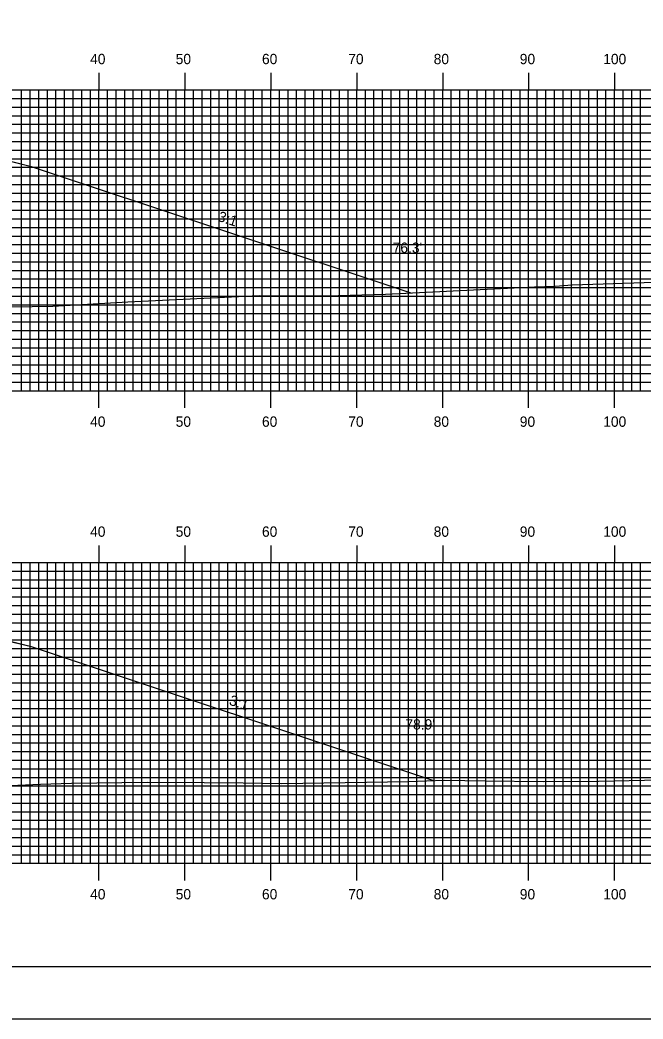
# Model space of a CAD drawing. Extents: x 1781860 to 1782203, y 442591 to 442811.
# Drawn here: x 1782056.7 to 1782129.2, y 442590.5 to 442706.8 of the extents above; entities that cross this region are included whole.
import ezdxf

# ---------------------------------------------------------------- set-up
doc = ezdxf.new("R2010")
doc.units = 0
for name, color, linetype in [('ANNOTATION', 7, 'Continuous'), ('BORDER', 7, 'Continuous'), ('D_Roadway_Centerline', 7, 'Continuous'), ('D_Roadway_SlopeLines', 7, 'Continuous'), ('D_Text_Standard', 7, 'Continuous'), ('H_V ANNOTATION', 7, 'Continuous'), ('MAJOR', 7, 'Continuous'), ('MINOR', 7, 'Continuous'), ('PLOT BOUNDARY', 7, 'Continuous'), ('S_Roadway_Centerline', 7, 'Continuous')]:
    doc.layers.add(name, color=color, linetype=linetype)

msp = doc.modelspace()

# ---------------------------------------------------------------- linework, layer by layer
at = {"layer": 'BORDER'}
msp.add_lwpolyline([(1781876.32, 442596.67), (1782196.32, 442596.67), (1782196.32, 442806.67), (1781876.32, 442806.67)], close=True, dxfattribs=at)
at = {"layer": 'D_Roadway_Centerline'}
for points in [[(1781943.58, 442673.02), (1781993.92, 442689.8), (1781995.75, 442690.26), (1782005.92, 442692.8), (1782013.92, 442693.12), (1782025.92, 442693.36), (1782037.92, 442693.12), (1782045.92, 442692.8), (1782056.09, 442690.26), (1782057.92, 442689.8), (1782102.21, 442675.04)], [(1781946.27, 442618.04), (1781993.92, 442633.93), (1781995.75, 442634.38), (1782005.92, 442636.93), (1782013.92, 442637.25), (1782025.92, 442637.49), (1782037.92, 442637.25), (1782045.92, 442636.93), (1782056.09, 442634.38), (1782057.92, 442633.93), (1782104.84, 442618.29)]]:
    msp.add_lwpolyline(points, dxfattribs=at)
at = {"layer": 'D_Roadway_SlopeLines'}
for points in [[(1782045.92, 442692.8), (1782057.92, 442689.8), (1782102.21, 442675.04)], [(1782045.92, 442636.93), (1782057.92, 442633.93), (1782104.84, 442618.29)]]:
    msp.add_lwpolyline(points, dxfattribs=at)
at = {"layer": 'MAJOR'}
for p, q in [((1782065.92, 442700.67), (1782065.92, 442698.67)), ((1782075.92, 442700.67), (1782075.92, 442698.67)), ((1782085.92, 442700.67), (1782085.92, 442698.67)), ((1782095.92, 442700.67), (1782095.92, 442698.67)), ((1782105.92, 442700.67), (1782105.92, 442698.67)), ((1782115.92, 442700.67), (1782115.92, 442698.67)), ((1782125.92, 442700.67), (1782125.92, 442698.67)), ((1781885.92, 442698.67), (1782165.92, 442698.67)), ((1781885.92, 442698.67), (1782165.92, 442698.67)), ((1782065.92, 442663.67), (1782065.92, 442698.67)), ((1782075.92, 442663.67), (1782075.92, 442698.67)), ((1782085.92, 442663.67), (1782085.92, 442698.67)), ((1782095.92, 442663.67), (1782095.92, 442698.67)), ((1782105.92, 442663.67), (1782105.92, 442698.67)), ((1782115.92, 442663.67), (1782115.92, 442698.67)), ((1782125.92, 442663.67), (1782125.92, 442698.67)), ((1781885.92, 442693.67), (1782165.92, 442693.67)), ((1781885.92, 442688.67), (1782165.92, 442688.67)), ((1781885.92, 442683.67), (1782165.92, 442683.67)), ((1781885.92, 442678.67), (1782165.92, 442678.67)), ((1781885.92, 442673.67), (1782165.92, 442673.67)), ((1781885.92, 442668.67), (1782165.92, 442668.67)), ((1781885.92, 442663.67), (1782165.92, 442663.67)), ((1781885.92, 442663.67), (1782165.92, 442663.67)), ((1782065.92, 442661.66), (1782065.92, 442663.67)), ((1782075.92, 442661.66), (1782075.92, 442663.67)), ((1782085.92, 442661.66), (1782085.92, 442663.67)), ((1782095.92, 442661.66), (1782095.92, 442663.67)), ((1782105.92, 442661.66), (1782105.92, 442663.67)), ((1782115.92, 442661.66), (1782115.92, 442663.67)), ((1782125.92, 442661.66), (1782125.92, 442663.67)), ((1782065.92, 442645.67), (1782065.92, 442643.67)), ((1782075.92, 442645.67), (1782075.92, 442643.67)), ((1782085.92, 442645.67), (1782085.92, 442643.67)), ((1782095.92, 442645.67), (1782095.92, 442643.67)), ((1782105.92, 442645.67), (1782105.92, 442643.67)), ((1782115.92, 442645.67), (1782115.92, 442643.67)), ((1782125.92, 442645.67), (1782125.92, 442643.67)), ((1781885.92, 442643.67), (1782165.92, 442643.67)), ((1781885.92, 442643.67), (1782165.92, 442643.67)), ((1782065.92, 442608.67), (1782065.92, 442643.67)), ((1782075.92, 442608.67), (1782075.92, 442643.67)), ((1782085.92, 442608.67), (1782085.92, 442643.67)), ((1782095.92, 442608.67), (1782095.92, 442643.67)), ((1782105.92, 442608.67), (1782105.92, 442643.67)), ((1782115.92, 442608.67), (1782115.92, 442643.67)), ((1782125.92, 442608.67), (1782125.92, 442643.67)), ((1781885.92, 442638.67), (1782165.92, 442638.67)), ((1781885.92, 442633.67), (1782165.92, 442633.67)), ((1781885.92, 442628.67), (1782165.92, 442628.67)), ((1781885.92, 442623.67), (1782165.92, 442623.67)), ((1781885.92, 442618.67), (1782165.92, 442618.67)), ((1781885.92, 442613.67), (1782165.92, 442613.67)), ((1781885.92, 442608.67), (1782165.92, 442608.67)), ((1781885.92, 442608.67), (1782165.92, 442608.67)), ((1782065.92, 442606.66), (1782065.92, 442608.67)), ((1782075.92, 442606.66), (1782075.92, 442608.67)), ((1782085.92, 442606.66), (1782085.92, 442608.67)), ((1782095.92, 442606.66), (1782095.92, 442608.67)), ((1782105.92, 442606.66), (1782105.92, 442608.67)), ((1782115.92, 442606.66), (1782115.92, 442608.67)), ((1782125.92, 442606.66), (1782125.92, 442608.67))]:
    msp.add_line(p, q, dxfattribs=at)
at = {"layer": 'MINOR'}
for p, q in [((1782056.92, 442663.67), (1782056.92, 442698.67)), ((1782057.92, 442663.67), (1782057.92, 442698.67)), ((1782058.92, 442663.67), (1782058.92, 442698.67)), ((1782059.92, 442663.67), (1782059.92, 442698.67)), ((1782060.92, 442663.67), (1782060.92, 442698.67)), ((1782061.92, 442663.67), (1782061.92, 442698.67)), ((1782062.92, 442663.67), (1782062.92, 442698.67)), ((1782063.92, 442663.67), (1782063.92, 442698.67)), ((1782064.92, 442663.67), (1782064.92, 442698.67)), ((1782066.92, 442663.67), (1782066.92, 442698.67)), ((1782067.92, 442663.67), (1782067.92, 442698.67)), ((1782068.92, 442663.67), (1782068.92, 442698.67)), ((1782069.92, 442663.67), (1782069.92, 442698.67)), ((1782070.92, 442663.67), (1782070.92, 442698.67)), ((1782071.92, 442663.67), (1782071.92, 442698.67)), ((1782072.92, 442663.67), (1782072.92, 442698.67)), ((1782073.92, 442663.67), (1782073.92, 442698.67)), ((1782074.92, 442663.67), (1782074.92, 442698.67)), ((1782076.92, 442663.67), (1782076.92, 442698.67)), ((1782077.92, 442663.67), (1782077.92, 442698.67)), ((1782078.92, 442663.67), (1782078.92, 442698.67)), ((1782079.92, 442663.67), (1782079.92, 442698.67)), ((1782080.92, 442663.67), (1782080.92, 442698.67)), ((1782081.92, 442663.67), (1782081.92, 442698.67)), ((1782082.92, 442663.67), (1782082.92, 442698.67)), ((1782083.92, 442663.67), (1782083.92, 442698.67)), ((1782084.92, 442663.67), (1782084.92, 442698.67)), ((1782086.92, 442663.67), (1782086.92, 442698.67)), ((1782087.92, 442663.67), (1782087.92, 442698.67)), ((1782088.92, 442663.67), (1782088.92, 442698.67)), ((1782089.92, 442663.67), (1782089.92, 442698.67)), ((1782090.92, 442663.67), (1782090.92, 442698.67)), ((1782091.92, 442663.67), (1782091.92, 442698.67)), ((1782092.92, 442663.67), (1782092.92, 442698.67)), ((1782093.92, 442663.67), (1782093.92, 442698.67)), ((1782094.92, 442663.67), (1782094.92, 442698.67)), ((1782096.92, 442663.67), (1782096.92, 442698.67)), ((1782097.92, 442663.67), (1782097.92, 442698.67)), ((1782098.92, 442663.67), (1782098.92, 442698.67)), ((1782099.92, 442663.67), (1782099.92, 442698.67)), ((1782100.92, 442663.67), (1782100.92, 442698.67)), ((1782101.92, 442663.67), (1782101.92, 442698.67)), ((1782102.92, 442663.67), (1782102.92, 442698.67)), ((1782103.92, 442663.67), (1782103.92, 442698.67)), ((1782104.92, 442663.67), (1782104.92, 442698.67)), ((1782106.92, 442663.67), (1782106.92, 442698.67)), ((1782107.92, 442663.67), (1782107.92, 442698.67)), ((1782108.92, 442663.67), (1782108.92, 442698.67)), ((1782109.92, 442663.67), (1782109.92, 442698.67)), ((1782110.92, 442663.67), (1782110.92, 442698.67)), ((1782111.92, 442663.67), (1782111.92, 442698.67)), ((1782112.92, 442663.67), (1782112.92, 442698.67)), ((1782113.92, 442663.67), (1782113.92, 442698.67)), ((1782114.92, 442663.67), (1782114.92, 442698.67)), ((1782116.92, 442663.67), (1782116.92, 442698.67)), ((1782117.92, 442663.67), (1782117.92, 442698.67)), ((1782118.92, 442663.67), (1782118.92, 442698.67)), ((1782119.92, 442663.67), (1782119.92, 442698.67)), ((1782120.92, 442663.67), (1782120.92, 442698.67)), ((1782121.92, 442663.67), (1782121.92, 442698.67)), ((1782122.92, 442663.67), (1782122.92, 442698.67)), ((1782123.92, 442663.67), (1782123.92, 442698.67)), ((1782124.92, 442663.67), (1782124.92, 442698.67)), ((1782126.92, 442663.67), (1782126.92, 442698.67)), ((1782127.92, 442663.67), (1782127.92, 442698.67)), ((1782128.92, 442663.67), (1782128.92, 442698.67)), ((1781885.92, 442697.67), (1782165.92, 442697.67)), ((1781885.92, 442696.67), (1782165.92, 442696.67)), ((1781885.92, 442695.67), (1782165.92, 442695.67)), ((1781885.92, 442694.67), (1782165.92, 442694.67)), ((1781885.92, 442692.67), (1782165.92, 442692.67)), ((1781885.92, 442691.67), (1782165.92, 442691.67)), ((1781885.92, 442690.67), (1782165.92, 442690.67)), ((1781885.92, 442689.67), (1782165.92, 442689.67)), ((1781885.92, 442687.67), (1782165.92, 442687.67)), ((1781885.92, 442686.67), (1782165.92, 442686.67)), ((1781885.92, 442685.67), (1782165.92, 442685.67)), ((1781885.92, 442684.67), (1782165.92, 442684.67)), ((1781885.92, 442682.67), (1782165.92, 442682.67)), ((1781885.92, 442681.67), (1782165.92, 442681.67)), ((1781885.92, 442680.67), (1782165.92, 442680.67)), ((1781885.92, 442679.67), (1782165.92, 442679.67)), ((1781885.92, 442677.67), (1782165.92, 442677.67)), ((1781885.92, 442676.67), (1782165.92, 442676.67)), ((1781885.92, 442675.67), (1782165.92, 442675.67)), ((1781885.92, 442674.67), (1782165.92, 442674.67)), ((1781885.92, 442672.67), (1782165.92, 442672.67)), ((1781885.92, 442671.67), (1782165.92, 442671.67)), ((1781885.92, 442670.67), (1782165.92, 442670.67)), ((1781885.92, 442669.67), (1782165.92, 442669.67)), ((1781885.92, 442667.67), (1782165.92, 442667.67)), ((1781885.92, 442666.67), (1782165.92, 442666.67)), ((1781885.92, 442665.67), (1782165.92, 442665.67)), ((1781885.92, 442664.67), (1782165.92, 442664.67)), ((1782056.92, 442608.67), (1782056.92, 442643.67)), ((1782057.92, 442608.67), (1782057.92, 442643.67)), ((1782058.92, 442608.67), (1782058.92, 442643.67)), ((1782059.92, 442608.67), (1782059.92, 442643.67)), ((1782060.92, 442608.67), (1782060.92, 442643.67)), ((1782061.92, 442608.67), (1782061.92, 442643.67)), ((1782062.92, 442608.67), (1782062.92, 442643.67)), ((1782063.92, 442608.67), (1782063.92, 442643.67)), ((1782064.92, 442608.67), (1782064.92, 442643.67)), ((1782066.92, 442608.67), (1782066.92, 442643.67)), ((1782067.92, 442608.67), (1782067.92, 442643.67)), ((1782068.92, 442608.67), (1782068.92, 442643.67)), ((1782069.92, 442608.67), (1782069.92, 442643.67)), ((1782070.92, 442608.67), (1782070.92, 442643.67)), ((1782071.92, 442608.67), (1782071.92, 442643.67)), ((1782072.92, 442608.67), (1782072.92, 442643.67)), ((1782073.92, 442608.67), (1782073.92, 442643.67)), ((1782074.92, 442608.67), (1782074.92, 442643.67)), ((1782076.92, 442608.67), (1782076.92, 442643.67)), ((1782077.92, 442608.67), (1782077.92, 442643.67)), ((1782078.92, 442608.67), (1782078.92, 442643.67)), ((1782079.92, 442608.67), (1782079.92, 442643.67)), ((1782080.92, 442608.67), (1782080.92, 442643.67)), ((1782081.92, 442608.67), (1782081.92, 442643.67)), ((1782082.92, 442608.67), (1782082.92, 442643.67)), ((1782083.92, 442608.67), (1782083.92, 442643.67)), ((1782084.92, 442608.67), (1782084.92, 442643.67)), ((1782086.92, 442608.67), (1782086.92, 442643.67)), ((1782087.92, 442608.67), (1782087.92, 442643.67)), ((1782088.92, 442608.67), (1782088.92, 442643.67)), ((1782089.92, 442608.67), (1782089.92, 442643.67)), ((1782090.92, 442608.67), (1782090.92, 442643.67)), ((1782091.92, 442608.67), (1782091.92, 442643.67)), ((1782092.92, 442608.67), (1782092.92, 442643.67)), ((1782093.92, 442608.67), (1782093.92, 442643.67)), ((1782094.92, 442608.67), (1782094.92, 442643.67)), ((1782096.92, 442608.67), (1782096.92, 442643.67)), ((1782097.92, 442608.67), (1782097.92, 442643.67)), ((1782098.92, 442608.67), (1782098.92, 442643.67)), ((1782099.92, 442608.67), (1782099.92, 442643.67)), ((1782100.92, 442608.67), (1782100.92, 442643.67)), ((1782101.92, 442608.67), (1782101.92, 442643.67)), ((1782102.92, 442608.67), (1782102.92, 442643.67)), ((1782103.92, 442608.67), (1782103.92, 442643.67)), ((1782104.92, 442608.67), (1782104.92, 442643.67)), ((1782106.92, 442608.67), (1782106.92, 442643.67)), ((1782107.92, 442608.67), (1782107.92, 442643.67)), ((1782108.92, 442608.67), (1782108.92, 442643.67)), ((1782109.92, 442608.67), (1782109.92, 442643.67)), ((1782110.92, 442608.67), (1782110.92, 442643.67)), ((1782111.92, 442608.67), (1782111.92, 442643.67)), ((1782112.92, 442608.67), (1782112.92, 442643.67)), ((1782113.92, 442608.67), (1782113.92, 442643.67)), ((1782114.92, 442608.67), (1782114.92, 442643.67)), ((1782116.92, 442608.67), (1782116.92, 442643.67)), ((1782117.92, 442608.67), (1782117.92, 442643.67)), ((1782118.92, 442608.67), (1782118.92, 442643.67)), ((1782119.92, 442608.67), (1782119.92, 442643.67)), ((1782120.92, 442608.67), (1782120.92, 442643.67)), ((1782121.92, 442608.67), (1782121.92, 442643.67)), ((1782122.92, 442608.67), (1782122.92, 442643.67)), ((1782123.92, 442608.67), (1782123.92, 442643.67)), ((1782124.92, 442608.67), (1782124.92, 442643.67)), ((1782126.92, 442608.67), (1782126.92, 442643.67)), ((1782127.92, 442608.67), (1782127.92, 442643.67)), ((1782128.92, 442608.67), (1782128.92, 442643.67)), ((1781885.92, 442642.67), (1782165.92, 442642.67)), ((1781885.92, 442641.67), (1782165.92, 442641.67)), ((1781885.92, 442640.67), (1782165.92, 442640.67)), ((1781885.92, 442639.67), (1782165.92, 442639.67)), ((1781885.92, 442637.67), (1782165.92, 442637.67)), ((1781885.92, 442636.67), (1782165.92, 442636.67)), ((1781885.92, 442635.67), (1782165.92, 442635.67)), ((1781885.92, 442634.67), (1782165.92, 442634.67)), ((1781885.92, 442632.67), (1782165.92, 442632.67)), ((1781885.92, 442631.67), (1782165.92, 442631.67)), ((1781885.92, 442630.67), (1782165.92, 442630.67)), ((1781885.92, 442629.67), (1782165.92, 442629.67)), ((1781885.92, 442627.67), (1782165.92, 442627.67)), ((1781885.92, 442626.67), (1782165.92, 442626.67)), ((1781885.92, 442625.67), (1782165.92, 442625.67)), ((1781885.92, 442624.67), (1782165.92, 442624.67)), ((1781885.92, 442622.67), (1782165.92, 442622.67)), ((1781885.92, 442621.67), (1782165.92, 442621.67)), ((1781885.92, 442620.67), (1782165.92, 442620.67)), ((1781885.92, 442619.67), (1782165.92, 442619.67)), ((1781885.92, 442617.67), (1782165.92, 442617.67)), ((1781885.92, 442616.67), (1782165.92, 442616.67)), ((1781885.92, 442615.67), (1782165.92, 442615.67)), ((1781885.92, 442614.67), (1782165.92, 442614.67)), ((1781885.92, 442612.67), (1782165.92, 442612.67)), ((1781885.92, 442611.67), (1782165.92, 442611.67)), ((1781885.92, 442610.67), (1782165.92, 442610.67)), ((1781885.92, 442609.67), (1782165.92, 442609.67))]:
    msp.add_line(p, q, dxfattribs=at)
at = {"layer": 'PLOT BOUNDARY'}
msp.add_lwpolyline([(1781860.13, 442590.55), (1782200.13, 442590.55), (1782200.13, 442810.55), (1781860.13, 442810.55)], close=True, dxfattribs=at)
at = {"layer": 'S_Roadway_Centerline'}
for points in [[(1782053.31, 442673.39), (1782060.57, 442673.51), (1782069.28, 442674.01), (1782084.58, 442674.76), (1782092.38, 442674.7), (1782099.26, 442674.89), (1782116.6, 442675.76), (1782118.99, 442675.82), (1782120.99, 442675.98), (1782138.96, 442676.59), (1782143, 442676.72), (1782152.54, 442677.3), (1782162.05, 442677.87), (1782165.92, 442678.07)], [(1782055.57, 442617.74), (1782059.11, 442617.89), (1782062.72, 442618.01), (1782071.54, 442618.1), (1782078.18, 442618.06), (1782082.71, 442618.05), (1782087.16, 442617.97), (1782101.99, 442618.18), (1782106.08, 442618.34), (1782110.89, 442618.27), (1782117.6, 442618.17), (1782124.05, 442618.24), (1782134.76, 442618.47), (1782146.14, 442618.76), (1782152.57, 442619.29), (1782159.39, 442619.5), (1782165.92, 442619.75)]]:
    msp.add_lwpolyline(points, dxfattribs=at)

# ---------------------------------------------------------------- texts
at = {"layer": 'ANNOTATION'}
for p in [(1782079.67, 442683.46), (1782080.98, 442627.15)]:
    msp.add_text('3:1', height=1.2, rotation=341.5652, dxfattribs=at).set_placement(p)
at = {"layer": 'D_Text_Standard'}
for s, p in [("76.3'", (1782100.1, 442679.71)), ("78.9'", (1782101.58, 442624.24))]:
    msp.add_text(s, height=1.2, dxfattribs=at).set_placement(p)
at = {"layer": 'H_V ANNOTATION'}
for s, p in [('40', (1782064.89, 442701.67)), ('50', (1782074.85, 442701.67)), ('60', (1782084.89, 442701.67)), ('70', (1782094.93, 442701.67)), ('80', (1782104.87, 442701.67)), ('90', (1782114.89, 442701.67)), ('100', (1782124.6, 442701.67)), ('40', (1782064.89, 442659.47)), ('50', (1782074.85, 442659.47)), ('60', (1782084.89, 442659.47)), ('70', (1782094.93, 442659.47)), ('80', (1782104.87, 442659.47)), ('90', (1782114.89, 442659.47)), ('100', (1782124.6, 442659.47)), ('40', (1782064.89, 442646.67)), ('50', (1782074.85, 442646.67)), ('60', (1782084.89, 442646.67)), ('70', (1782094.93, 442646.67)), ('80', (1782104.87, 442646.67)), ('90', (1782114.89, 442646.67)), ('100', (1782124.6, 442646.67)), ('40', (1782064.89, 442604.47)), ('50', (1782074.85, 442604.47)), ('60', (1782084.89, 442604.47)), ('70', (1782094.93, 442604.47)), ('80', (1782104.87, 442604.47)), ('90', (1782114.89, 442604.47)), ('100', (1782124.6, 442604.47))]:
    msp.add_text(s, height=1.2, dxfattribs=at).set_placement(p)

doc.saveas('drawing.dxf')
